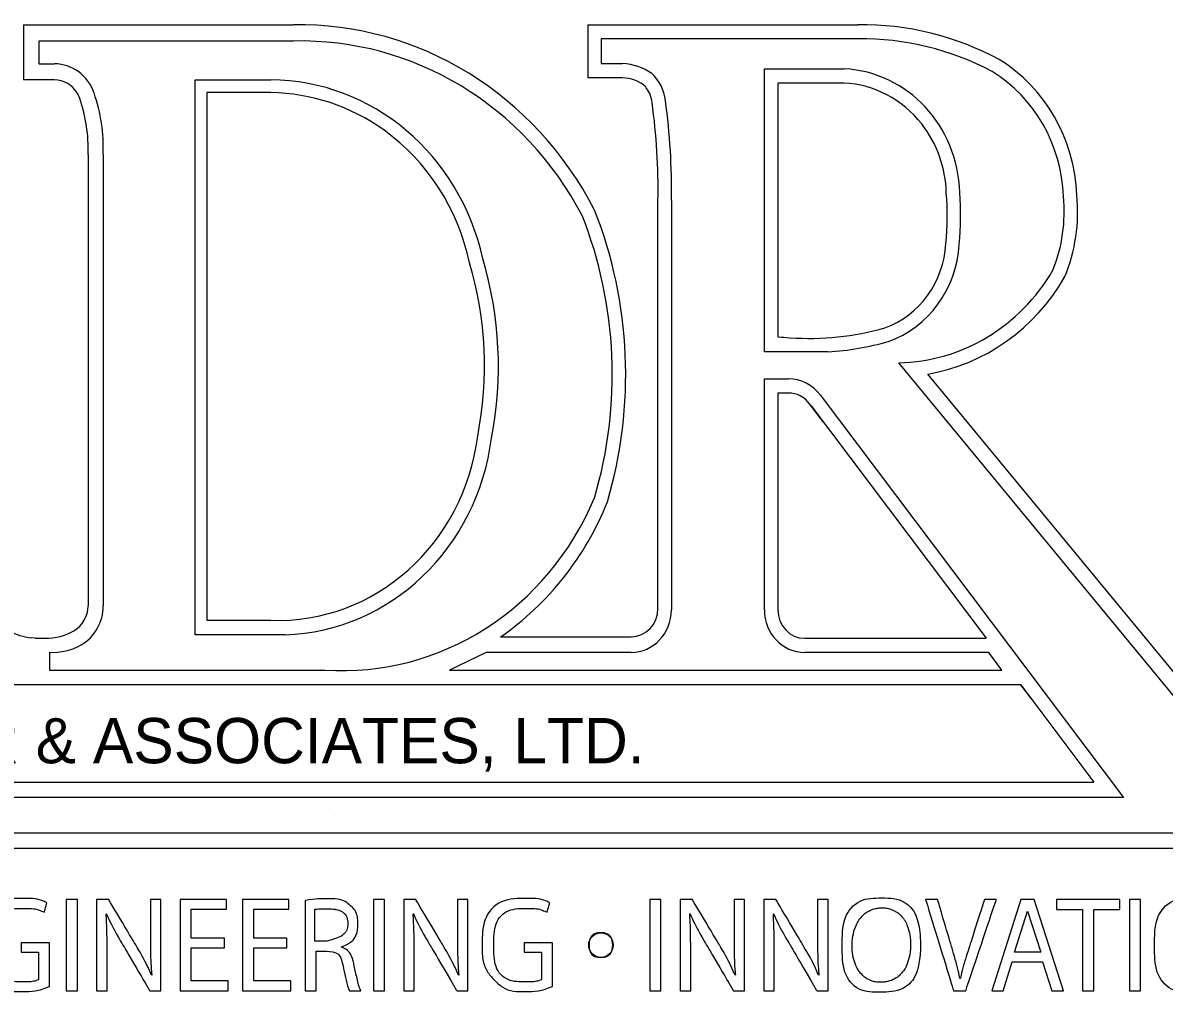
# Model space of a CAD drawing. Extents: x 0 to 34, y 0 to 22.
# Drawn here: x 32.53 to 33.336, y 3.375 to 4.06 of the extents above; entities that cross this region are included whole.
import ezdxf

# ---------------------------------------------------------------- set-up
doc = ezdxf.new("R2010")
doc.units = 0
doc.layers.add('SH_Data', color=7, linetype='Continuous')

msp = doc.modelspace()

# ---------------------------------------------------------------- linework, layer by layer
at = {"layer": 'SH_Data'}
for p, q in [((32.52996, 4.059), (32.52996, 4.02001)), ((32.52996, 4.059), (32.72096, 4.059)), ((32.92896, 4.059), (32.92896, 4.02146)), ((32.92896, 4.059), (33.11996, 4.059)), ((32.92896, 4.059), (32.92896, 4.02146)), ((32.92896, 4.059), (33.11996, 4.059)), ((32.54419, 4.02001), (32.52996, 4.02001)), ((32.55198, 4.02001), (32.54419, 4.02001)), ((32.94319, 4.02146), (32.92896, 4.02146)), ((32.94319, 4.02146), (32.92896, 4.02146)), ((32.95098, 4.02146), (32.94319, 4.02146)), ((32.70486, 4.01101), (32.65976, 4.01101)), ((32.65976, 4.01101), (32.65976, 3.63792)), ((32.57566, 3.96729), (32.57566, 3.64811)), ((32.97852, 3.64621), (32.97852, 3.93474)), ((33.38489, 3.55057), (33.16923, 3.81191)), ((33.08681, 3.78957), (33.2106, 3.62519)), ((32.65976, 3.63792), (32.66831, 3.63792)), ((32.66831, 3.63792), (32.70486, 3.63792)), ((32.53838, 3.62516), (32.53558, 3.62542)), ((32.53838, 3.62516), (32.53558, 3.62542)), ((32.53838, 3.62516), (32.54534, 3.62516)), ((32.86732, 3.62621), (32.95952, 3.62621)), ((33.08223, 3.62519), (33.2106, 3.62519)), ((33.23507, 3.59224), (33.28673, 3.52336)), ((32.21118, 3.52336), (33.28673, 3.52336)), ((32.75, 3.5), (32.75, 3.5)), ((33.44039, 3.47664), (32.07007, 3.47664)), ((32.7567, 3.4307), (32.75677, 3.43063)), ((33.2306, 3.40329), (33.23982, 3.43225)), ((33.23982, 3.43225), (33.24908, 3.40329)), ((32.75255, 3.4136), (32.74792, 3.41193)), ((32.73689, 3.41095), (32.73609, 3.41095)), ((32.74792, 3.41193), (32.74453, 3.41095)), ((32.75492, 3.40673), (32.75492, 3.40702)), ((33.24908, 3.40329), (33.2306, 3.40329)), ((32.76039, 3.376), (32.76847, 3.376))]:
    msp.add_line(p, q, dxfattribs=at)
for points in [[(32.72096, 4.04743), (32.54097, 4.04743), (32.54097, 4.03132), (32.55198, 4.03132)], [(33.11996, 4.049), (32.93846, 4.049), (32.93846, 4.03146), (32.95356, 4.03146)], [(33.05373, 4.02776), (33.11024, 4.02776)], [(33.09871, 3.82764), (33.05373, 3.82764), (33.05373, 4.02776)], [(32.65139, 3.62757), (32.65139, 4.02001), (32.70486, 4.02001)], [(33.11001, 4.01776), (33.06323, 4.01776), (33.06323, 3.83841)], [(32.58641, 3.96729), (32.58641, 3.96683), (32.58641, 3.64811)], [(32.98802, 3.93464), (32.98802, 3.64519)], [(33.37719, 3.54313), (33.14872, 3.82)], [(33.05373, 3.64519), (33.05373, 3.80857), (33.07085, 3.80857)], [(33.09319, 3.79721), (33.30749, 3.51264), (32.20382, 3.51264)], [(33.07085, 3.79857), (33.06323, 3.79857), (33.06323, 3.64519)], [(33.09537, 3.77821), (33.08574, 3.791)], [(32.71502, 3.62757), (32.65139, 3.62757)], [(32.86732, 3.62621), (32.88937, 3.62621)], [(33.08223, 3.62519), (33.08603, 3.62519)], [(32.54836, 3.61524), (32.54836, 3.60274), (32.74315, 3.60274)], [(32.95952, 3.61519), (32.85698, 3.61519), (32.83108, 3.60274), (33.22168, 3.60274), (33.21235, 3.61519), (33.08223, 3.61519)], [(33.24257, 3.58224), (33.23507, 3.59224), (32.24118, 3.59224), (32.20224, 3.52719)], [(32.06602, 3.50059), (32.06602, 3.48764), (33.42994, 3.48764), (33.42994, 3.50061)], [(32.72909, 3.43966), (32.72909, 3.376), (32.73689, 3.376), (32.73689, 3.40395), (32.74425, 3.40395)], [(33.25036, 3.39629), (33.25682, 3.376), (33.26516, 3.376), (33.24452, 3.44052), (33.23511, 3.44052), (33.21456, 3.376), (33.22263, 3.376), (33.22891, 3.39629), (33.25036, 3.39629)], [(32.74453, 3.41095), (32.74439, 3.41095), (32.74425, 3.41095)]]:
    msp.add_lwpolyline(points, dxfattribs=at)
msp.add_circle((32.93824, 3.40825), 0.00867, dxfattribs=at)
for centre, major_axis, start_param, end_param in [((32.72433, 3.80818), (0, 0.25085), 5.209873, 6.297313), ((33.12226, 3.8329), (0, 0.22611), 5.810103, 6.294452), ((33.12226, 3.8329), (0, 0.22611), 5.810103, 6.294452), ((32.72602, 3.80812), (0, 0.23937), 5.218006, 6.305445), ((33.12243, 3.83351), (0, 0.21551), 5.814829, 6.29527), ((33.16379, 3.93362), (0, 0.11672), 4.753214, 5.755325), ((33.16379, 3.93362), (0, 0.11672), 4.753214, 5.755325), ((32.55198, 4.00001), (0, 0.03131), 5.060756, 6.283185), ((32.95218, 3.98966), (0, 0.04182), 5.696071, 6.248499), ((33.10631, 3.93781), (0, 0.09005), 4.740194, 6.23721), ((33.16379, 3.93362), (0, 0.10672), 4.750292, 5.755325), ((32.55198, 4.00001), (0, 0.02), 5.294753, 6.283185), ((32.70388, 3.8572), (0, 0.16282), 4.938334, 6.276888), ((32.95218, 3.98966), (0, 0.03182), 5.717883, 6.322951), ((32.95511, 4.00164), (0, 0.03041), 4.832872, 5.561833), ((33.10631, 3.93781), (0, 0.08005), 5.402738, 6.234422), ((32.55198, 4.00001), (0, 0.02), 5.060756, 5.294753), ((32.47755, 3.97156), (0, 0.11467), 4.675194, 5.060756), ((32.70276, 3.85737), (0, 0.15366), 5.684676, 6.268828), ((32.95511, 4.00164), (0, 0.02041), 5.34604, 5.529903), ((32.95511, 4.00164), (0, 0.02041), 4.827568, 5.34604), ((32.95511, 4.00164), (0, 0.02041), 4.827568, 5.34604), ((32.47755, 3.97156), (0, 0.10336), 4.671123, 5.060756), ((32.57484, 3.94271), (0, 0.425), 4.693619, 4.857063), ((32.57484, 3.94271), (0, 0.425), 4.693619, 4.857063), ((32.57484, 3.94271), (0, 0.435), 4.693836, 4.856756), ((33.10631, 3.93781), (0, 0.08005), 4.740194, 5.402738), ((33.10631, 3.93781), (0, 0.08005), 4.740194, 5.402738), ((32.70276, 3.85737), (0, 0.15366), 4.930275, 5.684676), ((33.00347, 3.92393), (0, 0.18895), 4.608112, 4.797709), ((33.00347, 3.92393), (0, 0.18895), 4.608112, 4.797709), ((33.00861, 3.92385), (0, 0.19356), 4.607961, 4.797558), ((33.16601, 3.92655), (0, 0.10489), 4.309756, 4.818512), ((33.16601, 3.92655), (0, 0.11489), 4.303317, 4.815541), ((33.16601, 3.92655), (0, 0.11489), 4.303317, 4.815541), ((32.66751, 3.81165), (0, 0.2934), 4.410917, 5.105556), ((32.66751, 3.81165), (0, 0.3034), 4.410917, 5.105556), ((33.11824, 3.90826), (0, -0.06723), 0.330696, 1.511334), ((33.11824, 3.90826), (0, -0.06723), 0.330696, 1.511334), ((33.11779, 3.90865), (0, -0.07773), 0.32607, 1.506707), ((32.62458, 3.81762), (0, 0.24352), 4.507644, 5.016706), ((32.62601, 3.8177), (0, 0.25236), 4.509144, 5.018206), ((33.14666, 3.95705), (0, -0.13706), 0.015856, 1.021186), ((33.14666, 3.95705), (0, -0.14706), 0.16231, 1.026165), ((33.14666, 3.95705), (0, -0.14706), 0.16231, 1.026165), ((33.08509, 4.05603), (0, -0.21884), 6.219099, 6.545404), ((33.08509, 4.05603), (0, -0.21884), 6.219099, 6.545404), ((33.08509, 4.05603), (0, -0.21884), 6.177822, 6.219099), ((33.08509, 4.05603), (0, -0.22884), 0.06267, 0.262218), ((33.07085, 3.77857), (0, 0.03), 5.382662, 6.283185), ((33.07085, 3.77857), (0, 0.02), 5.382662, 6.283185), ((32.70994, 3.78768), (0, -0.14986), 6.247489, 7.723), ((32.70994, 3.78768), (0, -0.16019), 0.033392, 1.439815), ((32.75571, 3.80698), (0, -0.20467), 6.218561, 7.439351), ((32.75561, 3.80484), (0, -0.21386), 0.582172, 1.170799), ((32.55666, 3.64811), (0, -0.02), 0.497877, 1.570796), ((32.55666, 3.64811), (0, -0.03132), 0.497877, 1.570796), ((32.95952, 3.64621), (0, -0.02), 0, 1.570796), ((32.95952, 3.64519), (0, -0.03), 0, 1.570796), ((33.08223, 3.64519), (0, -0.03), 4.712389, 6.283185), ((33.08223, 3.64519), (0, -0.02), 4.712389, 6.283185), ((32.54013, 3.66951), (0, -0.04436), 5.785308, 6.174936), ((32.54561, 3.66951), (0, -0.04436), 6.276852, 6.781063), ((32.5506, 3.65985), (0, -0.04467), 6.230381, 6.780961)]:
    msp.add_ellipse(centre, major_axis=major_axis, ratio=0.95, start_param=start_param, end_param=end_param, dxfattribs=at)
for points, degree in [([(32.54839, 3.37887), (32.54489, 3.37753), (32.53798, 3.37533), (32.52982, 3.37533), (32.52067, 3.37533), (32.51313, 3.37782), (32.50721, 3.38385), (32.50201, 3.38921), (32.49878, 3.39783), (32.49878, 3.40788), (32.49887, 3.42712), (32.51125, 3.44119), (32.53152, 3.44119), (32.53852, 3.44119), (32.54399, 3.43956), (32.5466, 3.43822), (32.5466, 3.43822), (32.54471, 3.43142), (32.54471, 3.43142), (32.54148, 3.43295), (32.53745, 3.4342), (32.53134, 3.4342), (32.51663, 3.4342), (32.50703, 3.42444), (32.50703, 3.40826), (32.50703, 3.39189), (32.51627, 3.38222), (32.53036, 3.38222), (32.53547, 3.38222), (32.53897, 3.38299), (32.54077, 3.38395), (32.54077, 3.38395), (32.54077, 3.40319), (32.54077, 3.40319), (32.54077, 3.40319), (32.52847, 3.40319), (32.52847, 3.40319), (32.52847, 3.40319), (32.52847, 3.40989), (32.52847, 3.40989), (32.52847, 3.40989), (32.54839, 3.40989), (32.54839, 3.40989), (32.54839, 3.40989), (32.54839, 3.37887), (32.54839, 3.37887)], 3), ([(32.56813, 3.44052), (32.56813, 3.44052), (32.56813, 3.376), (32.56813, 3.376), (32.56813, 3.376), (32.56032, 3.376), (32.56032, 3.376), (32.56032, 3.376), (32.56032, 3.44052), (32.56032, 3.44052), (32.56032, 3.44052), (32.56813, 3.44052), (32.56813, 3.44052)], 3), ([(32.58177, 3.376), (32.58177, 3.376), (32.58177, 3.44052), (32.58177, 3.44052), (32.58177, 3.44052), (32.59029, 3.44052), (32.59029, 3.44052), (32.59029, 3.44052), (32.60967, 3.40788), (32.60967, 3.40788), (32.61416, 3.40031), (32.61766, 3.39352), (32.62053, 3.38691), (32.62053, 3.38691), (32.62071, 3.38701), (32.62071, 3.38701), (32.61999, 3.39562), (32.61981, 3.40347), (32.61981, 3.41352), (32.61981, 3.41352), (32.61981, 3.44052), (32.61981, 3.44052), (32.61981, 3.44052), (32.62717, 3.44052), (32.62717, 3.44052), (32.62717, 3.44052), (32.62717, 3.376), (32.62717, 3.376), (32.62717, 3.376), (32.61927, 3.376), (32.61927, 3.376), (32.61927, 3.376), (32.60007, 3.40874), (32.60007, 3.40874), (32.59585, 3.41592), (32.59182, 3.42329), (32.58876, 3.43027), (32.58876, 3.43027), (32.5885, 3.43018), (32.5885, 3.43018), (32.58894, 3.42204), (32.58912, 3.41429), (32.58912, 3.40357), (32.58912, 3.40357), (32.58912, 3.376), (32.58912, 3.376), (32.58912, 3.376), (32.58177, 3.376), (32.58177, 3.376)], 3), ([(32.67211, 3.40625), (32.67211, 3.40625), (32.64861, 3.40625), (32.64861, 3.40625), (32.64861, 3.40625), (32.64861, 3.38299), (32.64861, 3.38299), (32.64861, 3.38299), (32.67481, 3.38299), (32.67481, 3.38299), (32.67481, 3.38299), (32.67481, 3.376), (32.67481, 3.376), (32.67481, 3.376), (32.6408, 3.376), (32.6408, 3.376), (32.6408, 3.376), (32.6408, 3.44052), (32.6408, 3.44052), (32.6408, 3.44052), (32.67346, 3.44052), (32.67346, 3.44052), (32.67346, 3.44052), (32.67346, 3.43353), (32.67346, 3.43353), (32.67346, 3.43353), (32.64861, 3.43353), (32.64861, 3.43353), (32.64861, 3.43353), (32.64861, 3.41314), (32.64861, 3.41314), (32.64861, 3.41314), (32.67211, 3.41314), (32.67211, 3.41314), (32.67211, 3.41314), (32.67211, 3.40625), (32.67211, 3.40625)], 3), ([(32.71626, 3.40625), (32.71626, 3.40625), (32.69275, 3.40625), (32.69275, 3.40625), (32.69275, 3.40625), (32.69275, 3.38299), (32.69275, 3.38299), (32.69275, 3.38299), (32.71895, 3.38299), (32.71895, 3.38299), (32.71895, 3.38299), (32.71895, 3.376), (32.71895, 3.376), (32.71895, 3.376), (32.68494, 3.376), (32.68494, 3.376), (32.68494, 3.376), (32.68494, 3.44052), (32.68494, 3.44052), (32.68494, 3.44052), (32.7176, 3.44052), (32.7176, 3.44052), (32.7176, 3.44052), (32.7176, 3.43353), (32.7176, 3.43353), (32.7176, 3.43353), (32.69275, 3.43353), (32.69275, 3.43353), (32.69275, 3.43353), (32.69275, 3.41314), (32.69275, 3.41314), (32.69275, 3.41314), (32.71626, 3.41314), (32.71626, 3.41314), (32.71626, 3.41314), (32.71626, 3.40625), (32.71626, 3.40625)], 3), ([(32.75492, 3.40702), (32.76129, 3.40931), (32.76632, 3.41496), (32.76632, 3.42348), (32.76632, 3.42846), (32.76461, 3.43286), (32.76156, 3.43573), (32.7578, 3.43937), (32.75241, 3.44099), (32.74407, 3.44099), (32.73869, 3.44099), (32.73303, 3.44052), (32.72909, 3.43966)], 3), ([(32.78516, 3.44052), (32.78516, 3.44052), (32.78516, 3.376), (32.78516, 3.376), (32.78516, 3.376), (32.77735, 3.376), (32.77735, 3.376), (32.77735, 3.376), (32.77735, 3.44052), (32.77735, 3.44052), (32.77735, 3.44052), (32.78516, 3.44052), (32.78516, 3.44052)], 3), ([(32.79879, 3.376), (32.79879, 3.376), (32.79879, 3.44052), (32.79879, 3.44052), (32.79879, 3.44052), (32.80732, 3.44052), (32.80732, 3.44052), (32.80732, 3.44052), (32.8267, 3.40788), (32.8267, 3.40788), (32.83118, 3.40031), (32.83468, 3.39352), (32.83755, 3.38691), (32.83755, 3.38691), (32.83774, 3.38701), (32.83774, 3.38701), (32.83702, 3.39562), (32.83684, 3.40347), (32.83684, 3.41352), (32.83684, 3.41352), (32.83684, 3.44052), (32.83684, 3.44052), (32.83684, 3.44052), (32.84419, 3.44052), (32.84419, 3.44052), (32.84419, 3.44052), (32.84419, 3.376), (32.84419, 3.376), (32.84419, 3.376), (32.8363, 3.376), (32.8363, 3.376), (32.8363, 3.376), (32.8171, 3.40874), (32.8171, 3.40874), (32.81288, 3.41592), (32.80884, 3.42329), (32.80579, 3.43027), (32.80579, 3.43027), (32.80552, 3.43018), (32.80552, 3.43018), (32.80597, 3.42204), (32.80615, 3.41429), (32.80615, 3.40357), (32.80615, 3.40357), (32.80615, 3.376), (32.80615, 3.376), (32.80615, 3.376), (32.79879, 3.376), (32.79879, 3.376)], 3), ([(32.90386, 3.37887), (32.90036, 3.37753), (32.89345, 3.37533), (32.88529, 3.37533), (32.87613, 3.37533), (32.8686, 3.37782), (32.86267, 3.38385), (32.85747, 3.38921), (32.85424, 3.39783), (32.85424, 3.40788), (32.85433, 3.42712), (32.86671, 3.44119), (32.88699, 3.44119), (32.89399, 3.44119), (32.89946, 3.43956), (32.90206, 3.43822), (32.90206, 3.43822), (32.90018, 3.43142), (32.90018, 3.43142), (32.89695, 3.43295), (32.89291, 3.4342), (32.88681, 3.4342), (32.8721, 3.4342), (32.8625, 3.42444), (32.8625, 3.40826), (32.8625, 3.39189), (32.87174, 3.38222), (32.88582, 3.38222), (32.89094, 3.38222), (32.89444, 3.38299), (32.89623, 3.38395), (32.89623, 3.38395), (32.89623, 3.40319), (32.89623, 3.40319), (32.89623, 3.40319), (32.88394, 3.40319), (32.88394, 3.40319), (32.88394, 3.40319), (32.88394, 3.40989), (32.88394, 3.40989), (32.88394, 3.40989), (32.90386, 3.40989), (32.90386, 3.40989), (32.90386, 3.40989), (32.90386, 3.37887), (32.90386, 3.37887)], 3), ([(32.98065, 3.44052), (32.98065, 3.44052), (32.98065, 3.376), (32.98065, 3.376), (32.98065, 3.376), (32.97285, 3.376), (32.97285, 3.376), (32.97285, 3.376), (32.97285, 3.44052), (32.97285, 3.44052), (32.97285, 3.44052), (32.98065, 3.44052), (32.98065, 3.44052)], 3), ([(32.99429, 3.376), (32.99429, 3.376), (32.99429, 3.44052), (32.99429, 3.44052), (32.99429, 3.44052), (33.00282, 3.44052), (33.00282, 3.44052), (33.00282, 3.44052), (33.02219, 3.40788), (33.02219, 3.40788), (33.02668, 3.40031), (33.03018, 3.39352), (33.03305, 3.38691), (33.03305, 3.38691), (33.03323, 3.38701), (33.03323, 3.38701), (33.03251, 3.39562), (33.03234, 3.40347), (33.03234, 3.41352), (33.03234, 3.41352), (33.03234, 3.44052), (33.03234, 3.44052), (33.03234, 3.44052), (33.03969, 3.44052), (33.03969, 3.44052), (33.03969, 3.44052), (33.03969, 3.376), (33.03969, 3.376), (33.03969, 3.376), (33.03179, 3.376), (33.03179, 3.376), (33.03179, 3.376), (33.01259, 3.40874), (33.01259, 3.40874), (33.00838, 3.41592), (33.00434, 3.42329), (33.00129, 3.43027), (33.00129, 3.43027), (33.00102, 3.43018), (33.00102, 3.43018), (33.00147, 3.42204), (33.00165, 3.41429), (33.00165, 3.40357), (33.00165, 3.40357), (33.00165, 3.376), (33.00165, 3.376), (33.00165, 3.376), (32.99429, 3.376), (32.99429, 3.376)], 3), ([(33.05333, 3.376), (33.05333, 3.376), (33.05333, 3.44052), (33.05333, 3.44052), (33.05333, 3.44052), (33.06185, 3.44052), (33.06185, 3.44052), (33.06185, 3.44052), (33.08123, 3.40788), (33.08123, 3.40788), (33.08572, 3.40031), (33.08922, 3.39352), (33.09209, 3.38691), (33.09209, 3.38691), (33.09227, 3.38701), (33.09227, 3.38701), (33.09155, 3.39562), (33.09137, 3.40347), (33.09137, 3.41352), (33.09137, 3.41352), (33.09137, 3.44052), (33.09137, 3.44052), (33.09137, 3.44052), (33.09873, 3.44052), (33.09873, 3.44052), (33.09873, 3.44052), (33.09873, 3.376), (33.09873, 3.376), (33.09873, 3.376), (33.09083, 3.376), (33.09083, 3.376), (33.09083, 3.376), (33.07163, 3.40874), (33.07163, 3.40874), (33.06742, 3.41592), (33.06338, 3.42329), (33.06033, 3.43027), (33.06033, 3.43027), (33.06006, 3.43018), (33.06006, 3.43018), (33.0605, 3.42204), (33.06069, 3.41429), (33.06069, 3.40357), (33.06069, 3.40357), (33.06069, 3.376), (33.06069, 3.376), (33.06069, 3.376), (33.05333, 3.376), (33.05333, 3.376)], 3), ([(33.16405, 3.40893), (33.16405, 3.42807), (33.15337, 3.44157), (33.13686, 3.44157), (33.12071, 3.44157), (33.10878, 3.42817), (33.10878, 3.40768), (33.10878, 3.38816), (33.11999, 3.37495), (33.13596, 3.37495), (33.15139, 3.37495), (33.16405, 3.38672), (33.16405, 3.40893)], 3), ([(33.18746, 3.376), (33.18746, 3.376), (33.16772, 3.44052), (33.16772, 3.44052), (33.16772, 3.44052), (33.17616, 3.44052), (33.17616, 3.44052), (33.17616, 3.44052), (33.18558, 3.40874), (33.18558, 3.40874), (33.18818, 3.40003), (33.19042, 3.39218), (33.19204, 3.38461), (33.19204, 3.38461), (33.19222, 3.38461), (33.19222, 3.38461), (33.19392, 3.39208), (33.19643, 3.40022), (33.19912, 3.40864), (33.19912, 3.40864), (33.20935, 3.44052), (33.20935, 3.44052), (33.20935, 3.44052), (33.2177, 3.44052), (33.2177, 3.44052), (33.2177, 3.44052), (33.19608, 3.376), (33.19608, 3.376), (33.19608, 3.376), (33.18746, 3.376), (33.18746, 3.376)], 3), ([(33.27862, 3.43343), (33.27862, 3.43343), (33.26023, 3.43343), (33.26023, 3.43343), (33.26023, 3.43343), (33.26023, 3.44052), (33.26023, 3.44052), (33.26023, 3.44052), (33.305, 3.44052), (33.305, 3.44052), (33.305, 3.44052), (33.305, 3.43343), (33.305, 3.43343), (33.305, 3.43343), (33.28652, 3.43343), (33.28652, 3.43343), (33.28652, 3.43343), (33.28652, 3.376), (33.28652, 3.376), (33.28652, 3.376), (33.27862, 3.376), (33.27862, 3.376), (33.27862, 3.376), (33.27862, 3.43343), (33.27862, 3.43343)], 3), ([(33.31953, 3.44052), (33.31953, 3.44052), (33.31953, 3.376), (33.31953, 3.376), (33.31953, 3.376), (33.31173, 3.376), (33.31173, 3.376), (33.31173, 3.376), (33.31173, 3.44052), (33.31173, 3.44052), (33.31173, 3.44052), (33.31953, 3.44052), (33.31953, 3.44052)], 3), ([(33.38485, 3.40893), (33.38485, 3.42807), (33.37417, 3.44157), (33.35766, 3.44157), (33.34151, 3.44157), (33.32958, 3.42817), (33.32958, 3.40768), (33.32958, 3.38816), (33.34079, 3.37495), (33.35676, 3.37495), (33.3722, 3.37495), (33.38485, 3.38672), (33.38485, 3.40893)], 3), ([(32.73609, 3.43362), (32.73819, 3.43382), (32.74049, 3.43395), (32.74305, 3.43399), (32.74347, 3.43399), (32.74389, 3.43399), (32.74418, 3.43399), (32.74436, 3.43399), (32.74517, 3.43399), (32.74579, 3.43397), (32.74756, 3.43389), (32.74862, 3.43379), (32.75147, 3.43338), (32.75291, 3.43296), (32.75514, 3.43198), (32.75595, 3.43142), (32.7567, 3.4307)], 3), ([(32.73609, 3.41095), (32.73609, 3.41973), (32.73609, 3.42819), (32.73609, 3.43362)], 2), ([(32.75677, 3.43063), (32.75723, 3.4302), (32.75765, 3.42966), (32.7584, 3.42832), (32.75872, 3.42753), (32.75918, 3.4257), (32.75931, 3.42467), (32.75932, 3.42328), (32.75931, 3.42299), (32.75928, 3.42244), (32.75926, 3.42218), (32.75917, 3.42141), (32.75908, 3.42093), (32.75853, 3.41869), (32.75773, 3.41734), (32.75557, 3.41508), (32.75417, 3.41418), (32.75255, 3.4136)], 3), ([(33.11577, 3.40768), (33.11577, 3.41212), (33.11642, 3.41606), (33.11865, 3.42278), (33.12022, 3.42557), (33.12398, 3.43001), (33.12616, 3.43167), (33.12983, 3.43338), (33.13113, 3.43382), (33.13319, 3.43426), (33.13389, 3.43438), (33.13498, 3.43449), (33.13535, 3.43452), (33.1361, 3.43456), (33.13646, 3.43457), (33.14003, 3.43457), (33.14273, 3.43394), (33.14745, 3.43172), (33.14948, 3.43012), (33.15298, 3.42586), (33.15443, 3.42318), (33.15647, 3.41678), (33.15705, 3.41306), (33.15705, 3.40893)], 3), ([(32.94657, 3.40825), (32.94657, 3.40347), (32.94284, 3.39958), (32.93824, 3.39958), (32.93363, 3.39958), (32.92991, 3.40347), (32.92991, 3.40825), (32.92991, 3.41304), (32.93363, 3.41693), (32.93824, 3.41693), (32.94284, 3.41693), (32.94657, 3.41304), (32.94657, 3.40825)], 3), ([(32.74425, 3.41095), (32.74421, 3.41095), (32.73693, 3.41095), (32.73689, 3.41095)], 2), ([(32.76847, 3.376), (32.76721, 3.37849), (32.76578, 3.38471), (32.76381, 3.39371), (32.76237, 3.40041), (32.75959, 3.405), (32.75492, 3.40673)], 3), ([(33.15705, 3.40893), (33.15705, 3.40404), (33.15635, 3.39991), (33.15404, 3.39307), (33.15244, 3.39038), (33.14868, 3.38615), (33.14652, 3.38461), (33.14287, 3.38303), (33.14158, 3.38263), (33.13955, 3.38223), (33.13885, 3.38212), (33.13743, 3.38198), (33.13672, 3.38195), (33.13293, 3.38195), (33.13029, 3.38256), (33.1256, 3.38476), (33.12353, 3.38635), (33.11997, 3.39061), (33.11848, 3.39329), (33.11638, 3.39972), (33.11577, 3.40347), (33.11577, 3.40768)], 3), ([(32.74425, 3.40395), (32.75133, 3.40366), (32.75457, 3.40031), (32.75636, 3.39141), (32.75806, 3.38337), (32.75941, 3.37792), (32.76039, 3.376)], 3)]:
    msp.add_open_spline(points, degree=degree, dxfattribs=at)

# ---------------------------------------------------------------- texts
msp.add_text('ADR & ASSOCIATES, LTD.', height=0.0319999, dxfattribs=at).set_placement((32.43646, 3.5368))

doc.saveas('drawing.dxf')
